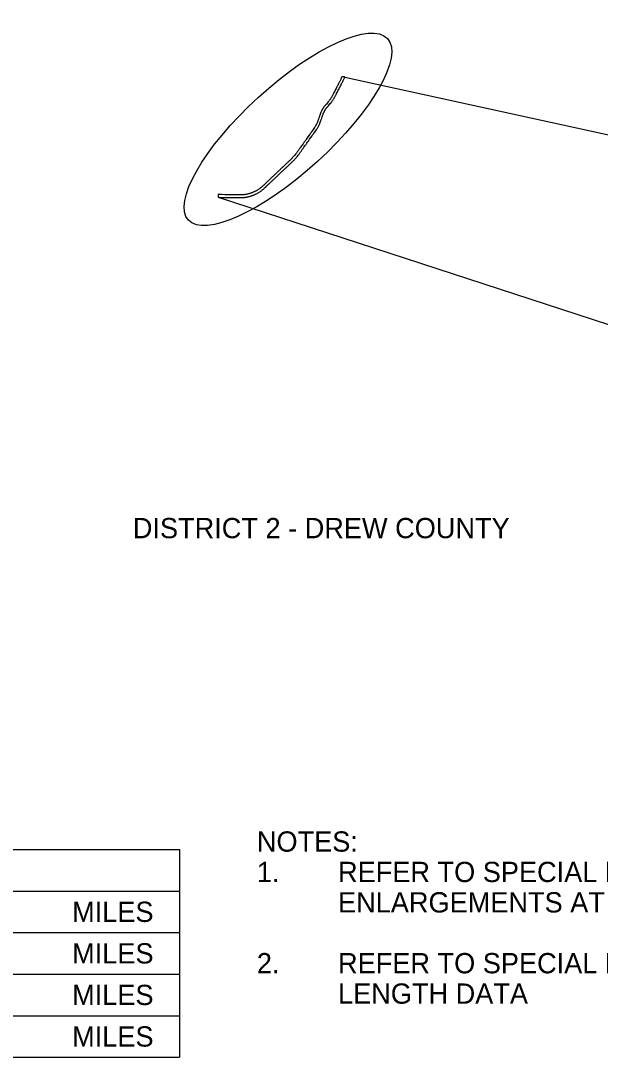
# Model space of a CAD drawing. Extents: x -2512 to 3792, y -435 to 2624.
# Drawn here: x 2037 to 2465, y 83 to 850 of the extents above; entities that cross this region are included whole.
import ezdxf

# ---------------------------------------------------------------- set-up
doc = ezdxf.new("R2010")
doc.units = 0
for name, color, linetype in [('3', 7, 'Continuous'), ('R_Annotation', 7, 'Continuous'), ('S_MISC_BOUNDARY', 7, 'Continuous')]:
    doc.layers.add(name, color=color, linetype=linetype)

msp = doc.modelspace()

# ---------------------------------------------------------------- linework, layer by layer
at = {"layer": '3'}
for p, q in [((1339.72, 236.44), (2154.19, 236.44)), ((2154.19, 236.44), (2154.19, 82.68)), ((1339.72, 205.69), (2154.19, 205.69)), ((1339.72, 174.94), (2154.19, 174.94)), ((1339.72, 144.18), (2154.19, 144.18)), ((1339.72, 113.43), (2154.19, 113.43)), ((1339.72, 82.68), (2154.19, 82.68))]:
    msp.add_line(p, q, dxfattribs=at)
at = {"layer": 'R_Annotation'}
for p, q in [((2276.46, 807.96), (2558.57, 746)), ((2182.89, 718.98), (2561.24, 595.44))]:
    msp.add_line(p, q, dxfattribs=at)
at = {"layer": 'S_MISC_BOUNDARY'}
msp.add_line((2182.93, 720.98), (2182.89, 718.98), dxfattribs=at)
for points in [[(2274.29, 808.02), (2274.08, 807.56), (2273.87, 807.07), (2273.67, 806.63), (2273.46, 806.16), (2273.2, 805.58), (2272.98, 805.12), (2272.77, 804.7)], [(2276.46, 807.96), (2276.27, 808.03), (2275.97, 808.12), (2275.87, 808.15), (2275.61, 808.17), (2275.45, 808.19), (2275.15, 808.18), (2274.77, 808.1), (2274.57, 808.08), (2274.29, 808.02)], [(2274.57, 803.82), (2274.78, 804.25), (2275.01, 804.74), (2275.28, 805.33), (2275.49, 805.81), (2275.69, 806.26), (2275.91, 806.74), (2276.46, 807.96)], [(2272.17, 803.53), (2271.94, 803.07), (2271.62, 802.46), (2271.23, 801.72), (2270.9, 801.07), (2270.45, 800.21), (2270.08, 799.49), (2269.64, 798.64), (2269.02, 797.46), (2268.68, 796.8), (2268.49, 796.43), (2268.24, 795.96), (2268.02, 795.53), (2267.8, 795.1), (2267.65, 794.82), (2267.5, 794.53), (2267.31, 794.17), (2267.07, 793.69), (2266.91, 793.39), (2266.77, 793.12), (2266.61, 792.85), (2266.45, 792.57), (2266.25, 792.23), (2266.01, 791.85), (2265.84, 791.6), (2265.64, 791.31), (2265.41, 790.99), (2265.21, 790.73), (2264.97, 790.42), (2264.76, 790.17), (2264.23, 789.54), (2262.87, 787.96), (2262.64, 787.7), (2262.43, 787.46), (2262.24, 787.24), (2262.08, 787.05), (2261.88, 786.82), (2261.7, 786.59), (2261.52, 786.37), (2261.34, 786.14), (2261.08, 785.79), (2260.96, 785.63), (2260.77, 785.35), (2260.66, 785.2), (2260.55, 785.03), (2260.45, 784.88), (2260.35, 784.72), (2260.23, 784.53), (2260.12, 784.35), (2259.95, 784.06), (2259.84, 783.87), (2259.74, 783.69), (2259.63, 783.49), (2259.47, 783.19), (2259.33, 782.92), (2259.17, 782.6), (2259.03, 782.29), (2258.87, 781.92), (2258.76, 781.66), (2258.64, 781.37), (2258.51, 781.05), (2258.35, 780.6), (2258.2, 780.16), (2257.99, 779.57), (2257.84, 779.12), (2257.68, 778.64), (2257.51, 778.17), (2257.34, 777.67), (2257.21, 777.29), (2257.05, 776.83), (2256.88, 776.35), (2256.74, 775.93), (2256.6, 775.54), (2256.47, 775.16), (2256.36, 774.85), (2256.22, 774.46), (2256.09, 774.12), (2255.9, 773.65), (2255.76, 773.34), (2255.6, 773.01), (2255.45, 772.7), (2255.29, 772.38), (2255.08, 772.01), (2254.92, 771.72), (2254.65, 771.27), (2254.44, 770.95), (2254.14, 770.49), (2253.66, 769.81), (2253.15, 769.1), (2252.67, 768.42), (2252.17, 767.73), (2251.72, 767.09), (2251.3, 766.49), (2250.72, 765.69), (2248.75, 762.91)], [(2250.5, 761.92), (2252.35, 764.53), (2252.93, 765.33), (2253.35, 765.93), (2253.8, 766.57), (2254.3, 767.26), (2254.78, 767.94), (2255.29, 768.65), (2255.78, 769.35), (2256.12, 769.85), (2256.35, 770.22), (2256.65, 770.71), (2256.83, 771.03), (2257.05, 771.44), (2257.24, 771.8), (2257.41, 772.14), (2257.58, 772.51), (2257.73, 772.87), (2257.95, 773.38), (2258.09, 773.75), (2258.25, 774.18), (2258.36, 774.5), (2258.49, 774.89), (2258.63, 775.28), (2258.77, 775.7), (2258.94, 776.18), (2259.1, 776.63), (2259.23, 777.02), (2259.4, 777.51), (2259.57, 777.99), (2259.73, 778.46), (2259.89, 778.91), (2260.09, 779.5), (2260.24, 779.93), (2260.39, 780.34), (2260.5, 780.63), (2260.61, 780.9), (2260.7, 781.13), (2260.85, 781.46), (2260.98, 781.74), (2261.12, 782.03), (2261.24, 782.27), (2261.39, 782.55), (2261.49, 782.72), (2261.58, 782.89), (2261.67, 783.05), (2261.83, 783.32), (2261.93, 783.48), (2262.04, 783.65), (2262.22, 783.93), (2262.32, 784.08), (2262.5, 784.34), (2262.69, 784.61), (2262.93, 784.92), (2263.09, 785.13), (2263.25, 785.33), (2263.42, 785.54), (2263.6, 785.75), (2263.75, 785.93), (2263.94, 786.15), (2264.15, 786.39), (2264.38, 786.66), (2265.75, 788.24), (2266.3, 788.88), (2266.53, 789.17), (2266.8, 789.51), (2267.02, 789.81), (2267.27, 790.15), (2267.5, 790.48), (2267.69, 790.76), (2267.95, 791.18), (2268.17, 791.55), (2268.35, 791.86), (2268.52, 792.17), (2268.68, 792.46), (2268.84, 792.77), (2269.09, 793.25), (2269.27, 793.6), (2269.43, 793.9), (2269.57, 794.18), (2269.79, 794.61), (2270.02, 795.04), (2270.26, 795.51), (2270.45, 795.88), (2270.8, 796.53), (2271.41, 797.72), (2271.85, 798.57), (2272.22, 799.29), (2272.67, 800.15), (2273.01, 800.8), (2273.4, 801.54), (2273.71, 802.15), (2273.95, 802.61), (2274.17, 803.04), (2274.37, 803.43), (2274.57, 803.82)], [(2272.77, 804.7), (2272.59, 804.34), (2272.4, 803.96), (2272.17, 803.53)], [(2248.75, 762.91), (2247.93, 761.76), (2247.6, 761.29), (2247.26, 760.82), (2246.88, 760.27), (2246.51, 759.76), (2246.26, 759.4), (2245.97, 759), (2245.68, 758.59), (2245.44, 758.26), (2244.89, 757.48), (2244.61, 757.09), (2244.06, 756.31), (2243.45, 755.45), (2243.13, 755.01), (2242.81, 754.56), (2242.45, 754.04), (2242.07, 753.51), (2241.7, 753), (2241.37, 752.53), (2241.03, 752.05), (2240.76, 751.69), (2240.42, 751.23), (2240.04, 750.75), (2239.6, 750.2), (2239.16, 749.68), (2238.36, 748.78), (2237.92, 748.3), (2237.51, 747.88), (2237.2, 747.57), (2236.93, 747.29), (2236.6, 746.98), (2236.26, 746.65), (2235.82, 746.23), (2235.4, 745.83), (2235.06, 745.51), (2234.73, 745.2), (2234.41, 744.9), (2234.03, 744.54), (2233.67, 744.19), (2233.25, 743.8), (2232.89, 743.46), (2232.56, 743.14), (2232.21, 742.81), (2231.93, 742.54), (2231.59, 742.22), (2231.21, 741.86), (2230.79, 741.46)], [(2232.16, 740.01), (2232.58, 740.41), (2232.96, 740.77), (2233.31, 741.09), (2233.59, 741.36), (2233.94, 741.69), (2234.27, 742.01), (2234.63, 742.34), (2235.04, 742.74), (2235.41, 743.09), (2235.79, 743.45), (2236.11, 743.75), (2236.44, 744.06), (2236.77, 744.38), (2237.2, 744.78), (2237.64, 745.2), (2237.99, 745.53), (2238.33, 745.86), (2238.62, 746.15), (2238.95, 746.49), (2239.37, 746.92), (2239.84, 747.43), (2240.68, 748.38), (2241.14, 748.93), (2241.6, 749.5), (2242.01, 750.02), (2242.37, 750.49), (2242.65, 750.88), (2243, 751.36), (2243.33, 751.84), (2243.7, 752.35), (2244.08, 752.89), (2244.44, 753.4), (2244.76, 753.85), (2245.08, 754.29), (2245.69, 755.15), (2246.24, 755.93), (2246.52, 756.32), (2247.07, 757.1), (2247.31, 757.43), (2247.6, 757.84), (2247.89, 758.24), (2248.14, 758.6), (2248.51, 759.12), (2248.89, 759.66), (2249.23, 760.13), (2249.56, 760.6), (2250.5, 761.92)], [(2192.1, 718.81), (2192.64, 718.8), (2194.68, 718.77), (2196.48, 718.73), (2197.33, 718.72), (2198.29, 718.7), (2198.74, 718.69), (2199.11, 718.69), (2199.47, 718.69), (2199.87, 718.7), (2200.18, 718.71), (2200.52, 718.73), (2200.85, 718.75), (2201.16, 718.77), (2201.43, 718.79), (2201.72, 718.82), (2201.97, 718.84), (2202.23, 718.87), (2202.47, 718.9), (2202.79, 718.95), (2203.14, 719), (2203.45, 719.05), (2203.77, 719.1), (2204.07, 719.16), (2204.36, 719.21), (2204.66, 719.28), (2204.98, 719.35), (2205.44, 719.46), (2205.81, 719.55), (2206.16, 719.65), (2206.54, 719.75), (2206.88, 719.85), (2207.17, 719.94), (2207.46, 720.04), (2207.77, 720.14), (2208.12, 720.27), (2208.43, 720.38), (2208.71, 720.49), (2209.01, 720.6), (2209.32, 720.74), (2209.67, 720.88), (2210.05, 721.05), (2210.44, 721.23), (2210.84, 721.42), (2211.23, 721.62), (2211.62, 721.82), (2211.93, 721.99), (2212.34, 722.23), (2212.56, 722.35), (2212.91, 722.56), (2213.31, 722.81), (2213.68, 723.05), (2214.09, 723.32), (2214.4, 723.53), (2214.8, 723.82), (2215.17, 724.1), (2215.53, 724.38), (2215.93, 724.69), (2216.29, 725), (2216.6, 725.27), (2216.94, 725.56), (2217.26, 725.86), (2217.64, 726.22), (2218, 726.57), (2218.82, 727.34), (2219.42, 727.91), (2219.84, 728.31), (2220.24, 728.69), (2220.67, 729.09), (2221.06, 729.46), (2221.41, 729.8), (2221.68, 730.06), (2222.01, 730.37), (2222.32, 730.66), (2222.64, 730.97), (2222.98, 731.29), (2223.28, 731.57), (2223.63, 731.91), (2223.96, 732.22), (2224.29, 732.54), (2224.66, 732.89), (2224.98, 733.19), (2225.32, 733.52), (2225.6, 733.78), (2225.93, 734.09), (2226.19, 734.34), (2226.59, 734.71), (2226.96, 735.06), (2227.3, 735.39), (2227.63, 735.71), (2228.02, 736.08), (2228.44, 736.48), (2228.84, 736.86), (2229.22, 737.21), (2229.58, 737.56), (2229.99, 737.94), (2230.45, 738.38), (2230.91, 738.82), (2231.38, 739.26), (2231.73, 739.6), (2232.16, 740.01)], [(2230.79, 741.46), (2230.36, 741.05), (2230, 740.71), (2229.53, 740.27), (2229.08, 739.83), (2228.61, 739.39), (2228.21, 739.01), (2227.84, 738.66), (2227.47, 738.31), (2227.07, 737.93), (2226.65, 737.53), (2226.26, 737.16), (2225.92, 736.84), (2225.58, 736.52), (2225.21, 736.16), (2224.81, 735.79), (2224.55, 735.54), (2224.22, 735.23), (2223.95, 734.97), (2223.61, 734.64), (2223.29, 734.34), (2222.92, 733.99), (2222.58, 733.67), (2222.25, 733.36), (2221.9, 733.02), (2221.6, 732.74), (2221.27, 732.42), (2220.95, 732.12), (2220.63, 731.82), (2220.31, 731.51), (2220.04, 731.25), (2219.68, 730.91), (2219.29, 730.54), (2218.87, 730.14), (2218.46, 729.76), (2218.04, 729.36), (2217.44, 728.79), (2216.63, 728.02), (2216.26, 727.67), (2215.89, 727.32), (2215.59, 727.05), (2215.28, 726.77), (2215, 726.52), (2214.66, 726.24), (2214.29, 725.95), (2213.96, 725.69), (2213.62, 725.44), (2213.24, 725.17), (2212.97, 724.98), (2212.58, 724.72), (2212.24, 724.5), (2211.87, 724.27), (2211.55, 724.08), (2211.35, 723.96), (2210.96, 723.74), (2210.68, 723.59), (2210.32, 723.4), (2209.96, 723.22), (2209.58, 723.04), (2209.23, 722.88), (2208.87, 722.72), (2208.55, 722.58), (2208.26, 722.46), (2207.99, 722.35), (2207.73, 722.25), (2207.44, 722.15), (2207.12, 722.03), (2206.83, 721.94), (2206.56, 721.85), (2206.29, 721.77), (2205.98, 721.67), (2205.63, 721.57), (2205.31, 721.49), (2204.96, 721.4), (2204.54, 721.3), (2204.24, 721.23), (2203.96, 721.18), (2203.69, 721.12), (2203.42, 721.07), (2203.13, 721.02), (2202.83, 720.97), (2202.51, 720.93), (2202.21, 720.89), (2202, 720.86), (2201.75, 720.83), (2201.52, 720.81), (2201.25, 720.78), (2201.01, 720.76), (2200.72, 720.74), (2200.41, 720.72), (2200.09, 720.71), (2199.82, 720.7), (2199.44, 720.69), (2199.11, 720.69), (2198.76, 720.69), (2198.32, 720.7), (2197.37, 720.72), (2196.52, 720.73), (2194.72, 720.76), (2192.67, 720.8), (2192.13, 720.81)], [(2192.13, 720.81), (2191.59, 720.82), (2189.88, 720.85), (2187.83, 720.89), (2185.43, 720.93), (2183.56, 720.97), (2182.93, 720.98)], [(2182.89, 718.98), (2183.53, 718.97), (2185.4, 718.93), (2187.79, 718.89), (2189.85, 718.85), (2191.55, 718.82), (2192.1, 718.81)]]:
    msp.add_lwpolyline(points, dxfattribs=at)
msp.add_ellipse((2234.46, 769.25), major_axis=(73.59, 67.19), ratio=0.323775, dxfattribs=at)

# ---------------------------------------------------------------- texts
at = {"layer": '3'}
for p in [(2074.92, 182.81), (2074.92, 152.06), (2074.92, 121.31), (2074.92, 90.56)]:
    msp.add_text('MILES', height=15.001, dxfattribs=at).set_placement(p)
at = {"layer": 'R_Annotation'}
for s, p in [('DISTRICT 2 - DREW COUNTY', (2119.8, 466.71)), ('NOTES:', (2211.49, 234.8)), ('1.', (2211.49, 212.3)), ('REFER TO SPECIAL DETAILS FOR INSET', (2271.49, 212.3)), ('ENLARGEMENTS AT SITE LOCATIONS', (2271.49, 189.8)), ('2.', (2211.49, 144.8)), ('REFER TO SPECIAL DETAILS FOR PROJECT', (2271.49, 144.8)), ('LENGTH DATA', (2271.49, 122.3))]:
    msp.add_text(s, height=15, dxfattribs=at).set_placement(p)

doc.saveas('drawing.dxf')
